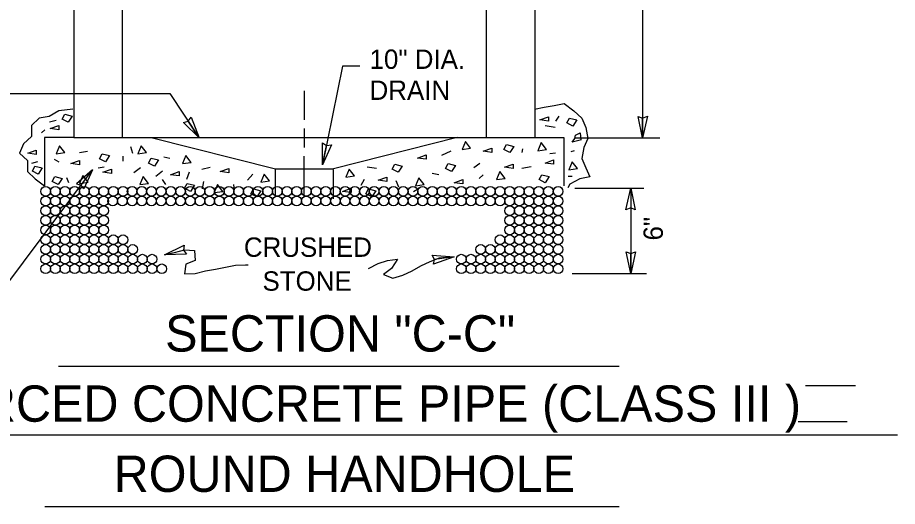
# Model space of a CAD drawing. Extents: x 19188 to 19495, y 20866 to 21061.
# Drawn here: x 19440.07 to 19478.14, y 21018.48 to 21039.63 of the extents above; entities that cross this region are included whole.
import ezdxf

# ---------------------------------------------------------------- set-up
doc = ezdxf.new("R2010")
doc.units = 0
doc.layers.add('G-ANNO-NOTE', color=7, linetype='Continuous')

msp = doc.modelspace()

# ---------------------------------------------------------------- linework, layer by layer
at = {"layer": 'G-ANNO-NOTE'}
for p, q in [((19442.5, 21052.496), (19442.5, 21034.451)), ((19462.449, 21052.496), (19462.449, 21034.451)), ((19467.119, 21051.931), (19467.119, 21034.434)), ((19444.594, 21047.573), (19444.594, 21034.451)), ((19460.354, 21047.573), (19460.354, 21034.451)), ((19454.13, 21037.528), (19453.268, 21033.26)), ((19454.877, 21037.528), (19454.13, 21037.528)), ((19435.796, 21036.355), (19446.658, 21036.355)), ((19446.658, 21036.355), (19447.922, 21034.434)), ((19452.474, 21036.466), (19452.474, 21035.207)), ((19442.003, 21035.234), (19442.118, 21035.448)), ((19442.118, 21035.448), (19442.434, 21035.368)), ((19442.434, 21035.368), (19442.262, 21035.101)), ((19462.664, 21035.207), (19463.038, 21035.341)), ((19463.038, 21035.341), (19463.038, 21035.154)), ((19463.498, 21035.368), (19463.354, 21035.154)), ((19441.744, 21035.181), (19441.457, 21035.101)), ((19441.486, 21034.834), (19441.86, 21034.968)), ((19441.86, 21034.968), (19441.86, 21034.781)), ((19442.262, 21035.101), (19442.003, 21035.234)), ((19447.922, 21034.434), (19447.454, 21035.146)), ((19463.038, 21035.154), (19462.664, 21035.207)), ((19462.894, 21034.968), (19463.326, 21034.888)), ((19463.843, 21035.074), (19463.957, 21035.288)), ((19464.101, 21034.941), (19463.843, 21035.074)), ((19463.957, 21035.288), (19464.274, 21035.207)), ((19464.274, 21035.207), (19464.101, 21034.941)), ((19467.119, 21034.434), (19467.119, 21035.287)), ((19441.256, 21034.781), (19441.112, 21034.648)), ((19441.86, 21034.781), (19441.486, 21034.834)), ((19452.474, 21034.834), (19452.474, 21034.007)), ((19464.217, 21034.541), (19464.417, 21034.648)), ((19464.417, 21034.648), (19464.446, 21034.327)), ((19442.5, 21034.451), (19441.243, 21034.451)), ((19441.243, 21034.451), (19441.243, 21032.356)), ((19442.5, 21034.451), (19462.449, 21034.451)), ((19445.851, 21034.451), (19451.225, 21033.091)), ((19459.097, 21034.451), (19453.738, 21033.091)), ((19459.446, 21034.274), (19459.303, 21033.927)), ((19459.676, 21033.981), (19459.446, 21034.274)), ((19462.449, 21034.451), (19463.706, 21034.451)), ((19462.722, 21034.221), (19462.579, 21033.874)), ((19462.952, 21033.927), (19462.722, 21034.221)), ((19463.706, 21034.451), (19463.706, 21032.356)), ((19464.073, 21034.247), (19464.188, 21034.407)), ((19464.417, 21034.327), (19464.073, 21034.247)), ((19464.188, 21034.407), (19464.217, 21034.541)), ((19464.188, 21034.434), (19467.866, 21034.434)), ((19440.509, 21033.767), (19440.882, 21033.901)), ((19440.882, 21033.901), (19440.882, 21033.714)), ((19441.888, 21034.087), (19441.744, 21033.74)), ((19442.118, 21033.794), (19441.888, 21034.087)), ((19442.75, 21033.794), (19443.095, 21033.847)), ((19444.963, 21034.061), (19445.049, 21033.767)), ((19445.423, 21034.087), (19445.279, 21033.74)), ((19445.653, 21033.794), (19445.423, 21034.087)), ((19453.268, 21033.26), (19453.437, 21034.096)), ((19458.814, 21033.847), (19458.412, 21033.66)), ((19459.303, 21033.927), (19459.676, 21033.981)), ((19460.222, 21033.847), (19460.595, 21033.981)), ((19460.595, 21033.794), (19460.222, 21033.847)), ((19460.595, 21033.981), (19460.595, 21033.794)), ((19461.112, 21033.927), (19461.228, 21034.141)), ((19461.372, 21033.794), (19461.112, 21033.927)), ((19461.228, 21034.141), (19461.544, 21034.061)), ((19461.544, 21034.061), (19461.372, 21033.794)), ((19461.917, 21033.954), (19461.889, 21033.794)), ((19462.579, 21033.874), (19462.952, 21033.927)), ((19464.159, 21033.874), (19464.015, 21033.821)), ((19440.882, 21033.714), (19440.509, 21033.767)), ((19441.658, 21033.501), (19441.86, 21033.394)), ((19441.744, 21033.74), (19442.118, 21033.794)), ((19442.377, 21033.314), (19442.75, 21033.447)), ((19442.75, 21033.447), (19442.75, 21033.26)), ((19443.612, 21033.527), (19443.727, 21033.74)), ((19443.871, 21033.394), (19443.612, 21033.527)), ((19443.727, 21033.74), (19444.043, 21033.66)), ((19444.043, 21033.66), (19443.871, 21033.394)), ((19444.646, 21033.421), (19444.646, 21033.634)), ((19445.279, 21033.74), (19445.653, 21033.794)), ((19445.739, 21033.34), (19445.854, 21033.554)), ((19445.854, 21033.554), (19446.17, 21033.474)), ((19446.17, 21033.474), (19445.997, 21033.207)), ((19446.4, 21033.607), (19446.658, 21033.554)), ((19447.348, 21033.66), (19447.204, 21033.314)), ((19447.578, 21033.367), (19447.348, 21033.66)), ((19452.474, 21031.87), (19452.474, 21033.634)), ((19457.377, 21033.554), (19457.75, 21033.687)), ((19457.75, 21033.501), (19457.377, 21033.554)), ((19457.75, 21033.687), (19457.75, 21033.501)), ((19462.894, 21033.34), (19463.268, 21033.474)), ((19463.354, 21033.767), (19463.096, 21033.74)), ((19463.268, 21033.474), (19463.268, 21033.287)), ((19440.94, 21033.394), (19440.681, 21033.314)), ((19440.71, 21032.993), (19440.825, 21033.207)), ((19440.825, 21033.207), (19441.141, 21033.127)), ((19441.141, 21033.127), (19440.969, 21032.86)), ((19442.75, 21033.26), (19442.377, 21033.314)), ((19443.555, 21033.127), (19443.814, 21033.181)), ((19443.756, 21032.94), (19444.129, 21033.074)), ((19444.129, 21033.074), (19444.129, 21032.887)), ((19445.394, 21033.127), (19445.106, 21032.914)), ((19445.997, 21033.207), (19445.739, 21033.34)), ((19447.204, 21033.314), (19447.578, 21033.367)), ((19448.038, 21033.074), (19448.411, 21033.154)), ((19448.842, 21032.967), (19449.216, 21033.101)), ((19449.216, 21033.101), (19449.216, 21032.914)), ((19451.217, 21033.062), (19451.217, 21031.87)), ((19451.225, 21033.091), (19453.738, 21033.091)), ((19453.731, 21033.062), (19453.731, 21031.791)), ((19454.417, 21033.074), (19454.274, 21032.727)), ((19454.647, 21032.78), (19454.417, 21033.074)), ((19455.595, 21033.101), (19455.193, 21033.154)), ((19456.285, 21033.074), (19456.4, 21033.287)), ((19456.544, 21032.94), (19456.285, 21033.074)), ((19456.4, 21033.287), (19456.716, 21033.207)), ((19456.716, 21033.207), (19456.544, 21032.94)), ((19458.584, 21033.101), (19458.699, 21033.314)), ((19458.843, 21032.967), (19458.584, 21033.101)), ((19458.699, 21033.314), (19459.015, 21033.234)), ((19459.015, 21033.234), (19458.843, 21032.967)), ((19460.078, 21033.314), (19459.82, 21033.127)), ((19461.141, 21033.154), (19461.515, 21033.287)), ((19461.515, 21033.101), (19461.141, 21033.154)), ((19461.515, 21033.287), (19461.515, 21033.101)), ((19462.291, 21033.181), (19461.889, 21033.101)), ((19463.268, 21033.287), (19462.894, 21033.34)), ((19464.073, 21033.394), (19463.929, 21033.047)), ((19463.929, 21033.047), (19464.302, 21033.101)), ((19464.302, 21033.101), (19464.073, 21033.394)), ((19440.969, 21032.86), (19440.71, 21032.993)), ((19441.572, 21032.54), (19441.687, 21032.754)), ((19441.687, 21032.754), (19442.003, 21032.674)), ((19442.003, 21032.674), (19441.831, 21032.407)), ((19442.291, 21032.487), (19442.204, 21032.7)), ((19442.894, 21032.807), (19442.75, 21032.46)), ((19443.124, 21032.514), (19442.894, 21032.807)), ((19444.129, 21032.887), (19443.756, 21032.94)), ((19445.509, 21032.754), (19445.365, 21032.407)), ((19445.739, 21032.46), (19445.509, 21032.754)), ((19446.342, 21032.993), (19446.055, 21032.754)), ((19446.687, 21032.834), (19447.061, 21032.967)), ((19447.061, 21032.78), (19446.687, 21032.834)), ((19447.061, 21032.967), (19447.061, 21032.78)), ((19447.491, 21032.94), (19447.377, 21032.62)), ((19449.216, 21032.914), (19448.842, 21032.967)), ((19450.25, 21032.86), (19450.02, 21032.594)), ((19450.739, 21032.86), (19450.595, 21032.514)), ((19450.969, 21032.567), (19450.739, 21032.86)), ((19454.274, 21032.727), (19454.647, 21032.78)), ((19455.681, 21032.594), (19456.055, 21032.727)), ((19456.055, 21032.727), (19456.055, 21032.54)), ((19457.435, 21032.7), (19457.291, 21032.354)), ((19457.665, 21032.407), (19457.435, 21032.7)), ((19458.296, 21032.834), (19458.009, 21032.887)), ((19460.05, 21032.674), (19460.222, 21032.834)), ((19460.941, 21032.967), (19460.797, 21032.62)), ((19460.797, 21032.62), (19461.17, 21032.674)), ((19461.17, 21032.674), (19460.941, 21032.967)), ((19462.636, 21032.62), (19462.75, 21032.834)), ((19462.75, 21032.834), (19463.067, 21032.754)), ((19463.067, 21032.754), (19462.894, 21032.487)), ((19464.073, 21032.754), (19463.9, 21032.754)), ((19441.831, 21032.407), (19441.572, 21032.54)), ((19442.75, 21032.46), (19443.124, 21032.514)), ((19445.365, 21032.407), (19445.739, 21032.46)), ((19446.486, 21032.407), (19446.342, 21032.62)), ((19447.291, 21032.247), (19447.405, 21032.46)), ((19447.405, 21032.46), (19447.722, 21032.381)), ((19447.722, 21032.381), (19447.549, 21032.113)), ((19448.066, 21032.22), (19448.124, 21032.54)), ((19448.727, 21032.407), (19448.584, 21032.06)), ((19448.957, 21032.113), (19448.727, 21032.407)), ((19449.417, 21032.407), (19449.446, 21032.167)), ((19450.595, 21032.514), (19450.969, 21032.567)), ((19454.934, 21032.38), (19455.078, 21032.647)), ((19456.055, 21032.54), (19455.681, 21032.594)), ((19456.572, 21032.3), (19456.458, 21032.567)), ((19457.291, 21032.354), (19457.665, 21032.407)), ((19458.957, 21032.487), (19459.331, 21032.62)), ((19459.331, 21032.434), (19458.957, 21032.487)), ((19459.331, 21032.62), (19459.331, 21032.434)), ((19462.894, 21032.487), (19462.636, 21032.62)), ((19447.549, 21032.113), (19447.291, 21032.247)), ((19448.584, 21032.06), (19448.957, 21032.113)), ((19450.164, 21032.007), (19450.279, 21032.22)), ((19450.423, 21031.873), (19450.164, 21032.007)), ((19450.279, 21032.22), (19450.595, 21032.14)), ((19450.595, 21032.14), (19450.423, 21031.873)), ((19454.13, 21032.113), (19454.503, 21032.247)), ((19454.503, 21032.06), (19454.13, 21032.113)), ((19454.503, 21032.247), (19454.503, 21032.06)), ((19455.136, 21032.007), (19455.25, 21032.22)), ((19455.394, 21031.873), (19455.136, 21032.007)), ((19455.25, 21032.22), (19455.567, 21032.14)), ((19455.567, 21032.14), (19455.394, 21031.873)), ((19457.197, 21032.113), (19457.455, 21032.247)), ((19464.188, 21032.247), (19467.176, 21032.247)), ((19466.602, 21032.247), (19466.602, 21028.566)), ((19466.602, 21032.247), (19466.602, 21031.394)), ((19446.428, 21029.366), (19447.256, 21029.571)), ((19458.957, 21029.286), (19458.114, 21029.159)), ((19466.602, 21028.566), (19466.602, 21029.419)), ((19464.073, 21028.566), (19467.291, 21028.566)), ((19441.847, 21024.549), (19466.107, 21024.549)), ((19474.164, 21023.718), (19476.324, 21023.718)), ((19473.849, 21022.153), (19475.964, 21022.153)), ((19428.442, 21021.575), (19478.142, 21021.575)), ((19441.258, 21018.48), (19466.107, 21018.48))]:
    msp.add_line(p, q, dxfattribs=at)
for points in [[(19462.437, 21035.674), (19462.864, 21035.753), (19463.29, 21035.832), (19463.717, 21035.911), (19464.145, 21035.594), (19464.486, 21035.277), (19464.657, 21034.881), (19464.742, 21034.406), (19464.571, 21034.01), (19464.486, 21033.534), (19464.657, 21033.137), (19464.827, 21032.741), (19464.4, 21032.662), (19463.974, 21032.425), (19463.888, 21032.266)], [(19442.46, 21035.674), (19441.862, 21035.594), (19441.435, 21035.356), (19441.008, 21035.277), (19440.667, 21034.96), (19440.667, 21034.485), (19440.326, 21034.168), (19440.155, 21033.772), (19440.496, 21033.455), (19440.496, 21032.979), (19440.838, 21032.662), (19441.243, 21032.356)], [(19467.119, 21035.287), (19467.322, 21035.362), (19467.119, 21034.434), (19466.924, 21035.36), (19467.119, 21035.287)], [(19447.454, 21035.146), (19447.583, 21035.321), (19447.922, 21034.434), (19447.251, 21035.1), (19447.454, 21035.146)], [(19453.437, 21034.097), (19453.651, 21034.129), (19453.268, 21033.26), (19453.26, 21034.207), (19453.437, 21034.097)], [(19426.568, 21026.367), (19438.302, 21026.367), (19443.319, 21033.045)], [(19466.602, 21031.394), (19466.398, 21031.319), (19466.602, 21032.247), (19466.796, 21031.321), (19466.602, 21031.394)], [(19447.256, 21029.571), (19447.378, 21029.391), (19446.428, 21029.366), (19447.28, 21029.778), (19447.256, 21029.571)], [(19446.428, 21029.366), (19446.86, 21029.473), (19447.291, 21029.58), (19447.722, 21029.553), (19447.751, 21029.126), (19447.348, 21028.966), (19447.291, 21028.539), (19447.751, 21028.566), (19448.21, 21028.673), (19448.641, 21028.753), (19449.072, 21028.833), (19449.503, 21028.913), (19449.934, 21028.939), (19450.049, 21028.939)], [(19455.25, 21028.78), (19455.681, 21028.993), (19456.084, 21029.126), (19456.515, 21029.179), (19456.256, 21028.78), (19455.912, 21028.513), (19456.314, 21028.353), (19456.745, 21028.486), (19457.147, 21028.673), (19457.521, 21028.886), (19457.923, 21029.073), (19458.325, 21029.233), (19458.756, 21029.286), (19458.957, 21029.286)], [(19458.114, 21029.159), (19458.01, 21029.349), (19458.957, 21029.286), (19458.071, 21028.956), (19458.114, 21029.159)], [(19466.602, 21029.419), (19466.805, 21029.494), (19466.602, 21028.566), (19466.407, 21029.492), (19466.602, 21029.419)]]:
    msp.add_lwpolyline(points, dxfattribs=at)
msp.add_lwpolyline([(19442.622, 21032.446), (19442.824, 21032.386), (19443.319, 21033.045), (19442.932, 21032.216), (19442.824, 21032.386), (19443.319, 21033.045)], close=True, dxfattribs=at)
for centre in [(19441.285, 21032.114), (19441.704, 21032.114), (19442.122, 21032.114), (19442.541, 21032.114), (19442.96, 21032.114), (19443.379, 21032.114), (19443.798, 21032.114), (19444.217, 21032.114), (19444.636, 21032.114), (19445.028, 21032.114), (19445.447, 21032.114), (19445.866, 21032.114), (19446.285, 21032.114), (19446.704, 21032.114), (19447.123, 21032.114), (19447.542, 21032.114), (19447.961, 21032.114), (19448.38, 21032.114), (19448.799, 21032.114), (19449.217, 21032.114), (19449.636, 21032.114), (19450.055, 21032.114), (19450.474, 21032.114), (19450.893, 21032.114), (19451.312, 21032.114), (19451.731, 21032.114), (19452.15, 21032.114), (19452.569, 21032.114), (19452.988, 21032.114), (19453.407, 21032.114), (19453.826, 21032.114), (19454.245, 21032.114), (19454.664, 21032.114), (19455.082, 21032.114), (19455.501, 21032.114), (19455.92, 21032.114), (19456.339, 21032.114), (19456.758, 21032.114), (19457.177, 21032.114), (19457.596, 21032.114), (19458.015, 21032.114), (19458.434, 21032.114), (19458.853, 21032.114), (19459.272, 21032.114), (19459.691, 21032.114), (19460.11, 21032.114), (19460.528, 21032.114), (19460.947, 21032.114), (19461.366, 21032.114), (19461.785, 21032.114), (19462.204, 21032.114), (19462.623, 21032.114), (19463.042, 21032.114), (19463.461, 21032.114), (19441.285, 21031.695), (19441.704, 21031.695), (19442.122, 21031.695), (19442.541, 21031.695), (19442.96, 21031.695), (19443.379, 21031.695), (19443.798, 21031.695), (19444.19, 21031.695), (19444.609, 21031.695), (19445.028, 21031.695), (19445.447, 21031.695), (19445.866, 21031.695), (19446.285, 21031.695), (19446.704, 21031.695), (19447.123, 21031.695), (19447.542, 21031.695), (19447.961, 21031.695), (19448.38, 21031.695), (19448.799, 21031.695), (19449.217, 21031.695), (19449.636, 21031.695), (19450.055, 21031.695), (19450.474, 21031.695), (19450.893, 21031.695), (19451.312, 21031.695), (19451.731, 21031.695), (19452.15, 21031.695), (19452.569, 21031.695), (19452.988, 21031.695), (19453.407, 21031.695), (19453.826, 21031.695), (19454.245, 21031.695), (19454.664, 21031.695), (19455.082, 21031.695), (19455.501, 21031.695), (19455.92, 21031.695), (19456.339, 21031.695), (19456.758, 21031.695), (19457.177, 21031.695), (19457.596, 21031.695), (19458.015, 21031.695), (19458.434, 21031.695), (19458.853, 21031.695), (19459.272, 21031.695), (19459.691, 21031.695), (19460.11, 21031.695), (19460.528, 21031.695), (19460.947, 21031.695), (19461.366, 21031.695), (19461.785, 21031.695), (19462.204, 21031.695), (19462.623, 21031.695), (19463.042, 21031.695), (19463.461, 21031.695), (19441.285, 21031.276), (19441.704, 21031.276), (19442.122, 21031.276), (19442.541, 21031.276), (19442.96, 21031.276), (19443.379, 21031.276), (19443.798, 21031.276), (19461.366, 21031.276), (19461.785, 21031.276), (19462.204, 21031.276), (19462.623, 21031.276), (19463.042, 21031.276), (19463.461, 21031.276), (19441.285, 21030.857), (19441.704, 21030.857), (19442.122, 21030.857), (19442.541, 21030.857), (19442.96, 21030.857), (19443.379, 21030.857), (19443.798, 21030.857), (19461.366, 21030.857), (19461.785, 21030.857), (19462.204, 21030.857), (19462.623, 21030.857), (19463.042, 21030.857), (19463.461, 21030.857), (19441.285, 21030.438), (19441.704, 21030.438), (19442.122, 21030.438), (19442.541, 21030.438), (19442.96, 21030.438), (19443.379, 21030.438), (19443.798, 21030.438), (19461.366, 21030.438), (19461.785, 21030.438), (19462.204, 21030.438), (19462.623, 21030.438), (19463.042, 21030.438), (19463.461, 21030.438), (19441.285, 21030.019), (19441.704, 21030.019), (19442.122, 21030.019), (19442.541, 21030.019), (19442.96, 21030.019), (19443.379, 21030.019), (19443.798, 21030.019), (19444.217, 21030.019), (19444.636, 21030.019), (19460.947, 21030.019), (19461.366, 21030.019), (19461.785, 21030.019), (19462.204, 21030.019), (19462.623, 21030.019), (19463.042, 21030.019), (19463.461, 21030.019), (19441.285, 21029.6), (19441.704, 21029.6), (19442.122, 21029.6), (19442.541, 21029.6), (19442.96, 21029.6), (19443.379, 21029.6), (19443.798, 21029.6), (19444.217, 21029.6), (19444.636, 21029.6), (19445.055, 21029.6), (19460.11, 21029.6), (19460.528, 21029.6), (19460.947, 21029.6), (19461.366, 21029.6), (19461.785, 21029.6), (19462.204, 21029.6), (19462.623, 21029.6), (19463.042, 21029.6), (19463.461, 21029.6), (19441.285, 21029.181), (19441.704, 21029.181), (19442.122, 21029.181), (19442.541, 21029.181), (19442.96, 21029.181), (19443.379, 21029.181), (19443.798, 21029.181), (19444.217, 21029.181), (19444.636, 21029.181), (19445.055, 21029.181), (19445.474, 21029.181), (19445.893, 21029.181), (19459.272, 21029.181), (19459.691, 21029.181), (19460.11, 21029.181), (19460.528, 21029.181), (19460.947, 21029.181), (19461.366, 21029.181), (19461.785, 21029.181), (19462.204, 21029.181), (19462.623, 21029.181), (19463.042, 21029.181), (19463.461, 21029.181), (19441.285, 21028.762), (19441.704, 21028.762), (19442.122, 21028.762), (19442.541, 21028.762), (19442.96, 21028.762), (19443.379, 21028.762), (19443.798, 21028.762), (19444.217, 21028.762), (19444.636, 21028.762), (19445.055, 21028.762), (19445.474, 21028.762), (19445.893, 21028.762), (19446.312, 21028.762), (19459.272, 21028.762), (19459.691, 21028.762), (19460.11, 21028.762), (19460.528, 21028.762), (19460.947, 21028.762), (19461.366, 21028.762), (19461.785, 21028.762), (19462.204, 21028.762), (19462.623, 21028.762), (19463.042, 21028.762), (19463.461, 21028.762), (19463.461, 21028.762)]:
    msp.add_circle(centre, 0.209, dxfattribs=at)

# ---------------------------------------------------------------- texts
for s, height, p in [('10" DIA.', 0.8379, (19455.302, 21037.414)), ('DRAIN', 0.8379, (19455.302, 21036.073)), ('CRUSHED', 0.8379, (19449.865, 21029.28)), ('STONE', 0.8379, (19450.669, 21027.814)), ('SECTION "C-C"', 1.57098, (19446.456, 21025.181)), ('REINFORCED CONCRETE PIPE (CLASS III )', 1.57098, (19430.549, 21022.144)), ('ROUND HANDHOLE', 1.57098, (19444.23, 21019.107))]:
    msp.add_text(s, height=height, dxfattribs=at).set_placement(p)
msp.add_text('6"', height=0.8379, rotation=90, dxfattribs=at).set_placement((19467.994, 21029.987))

doc.saveas('drawing.dxf')
